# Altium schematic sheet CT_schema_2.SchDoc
size 493 x 398 mm
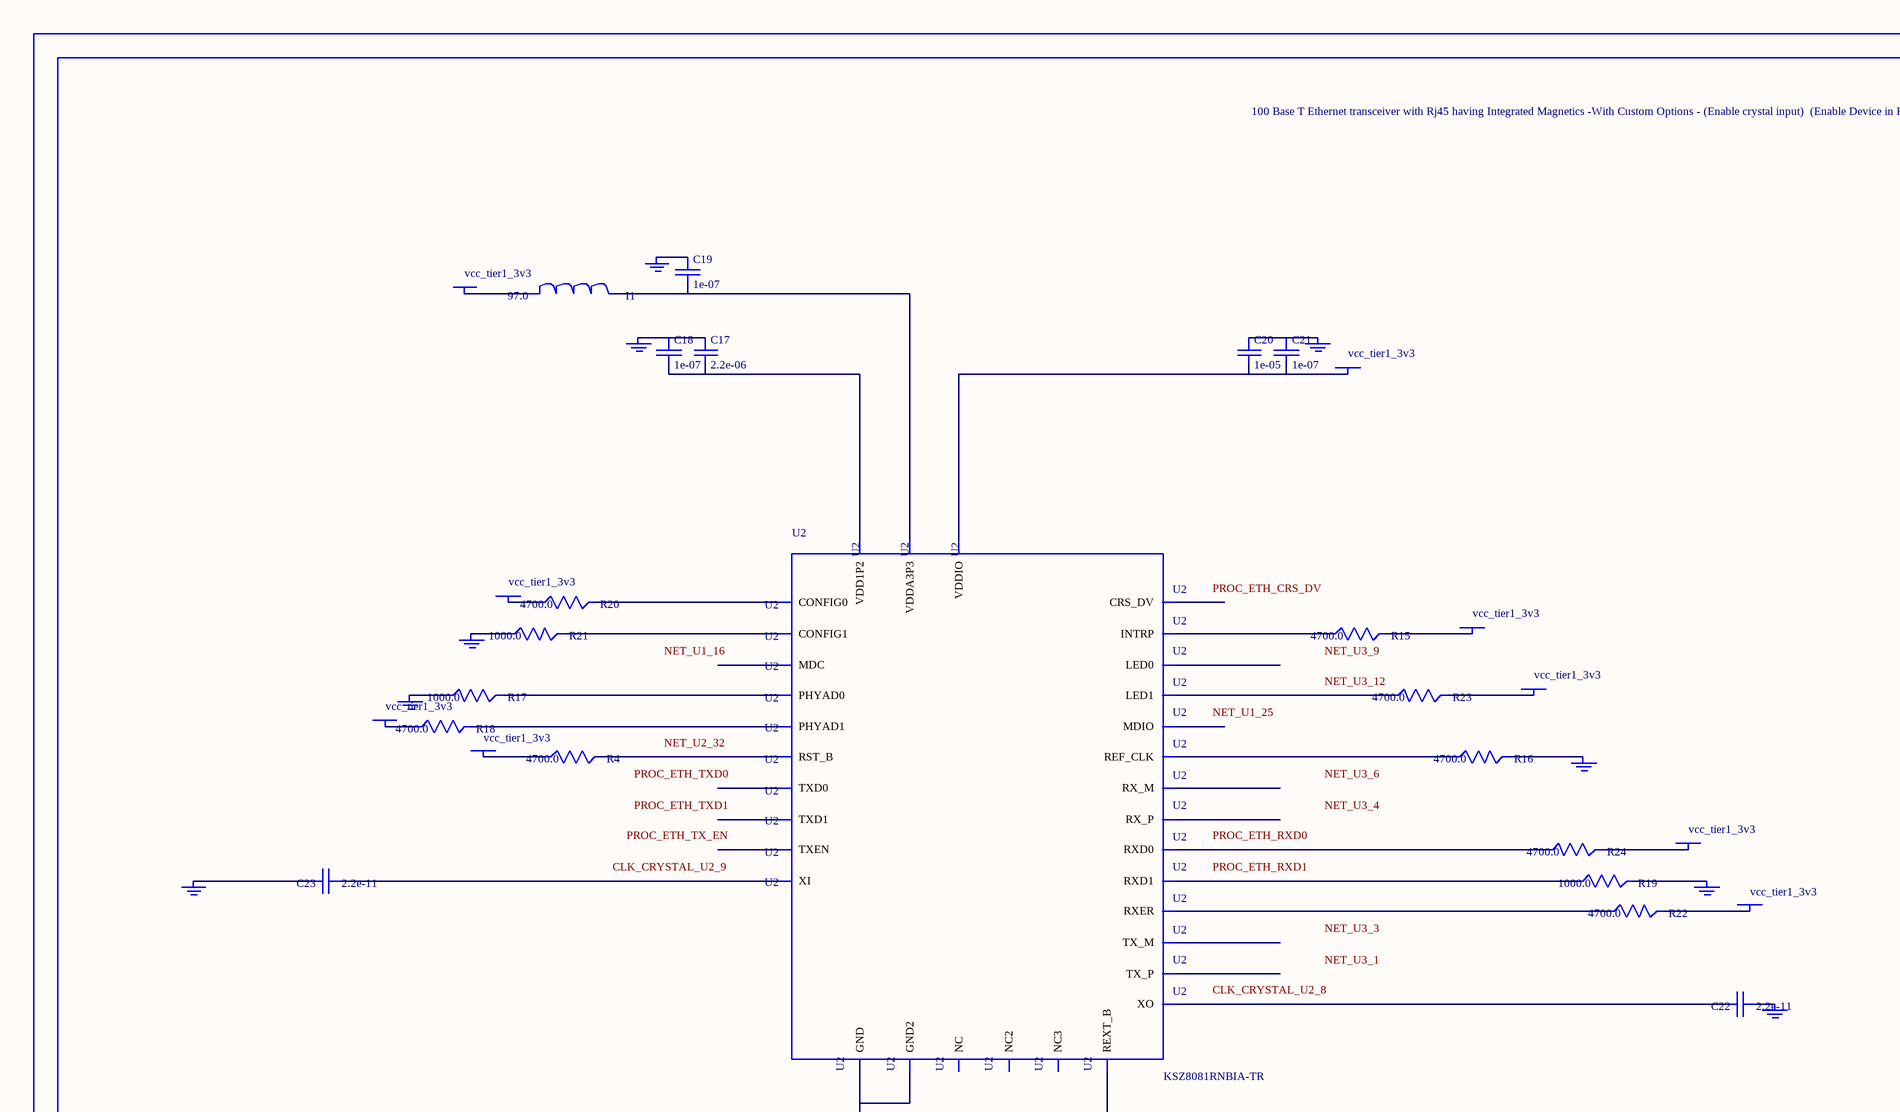
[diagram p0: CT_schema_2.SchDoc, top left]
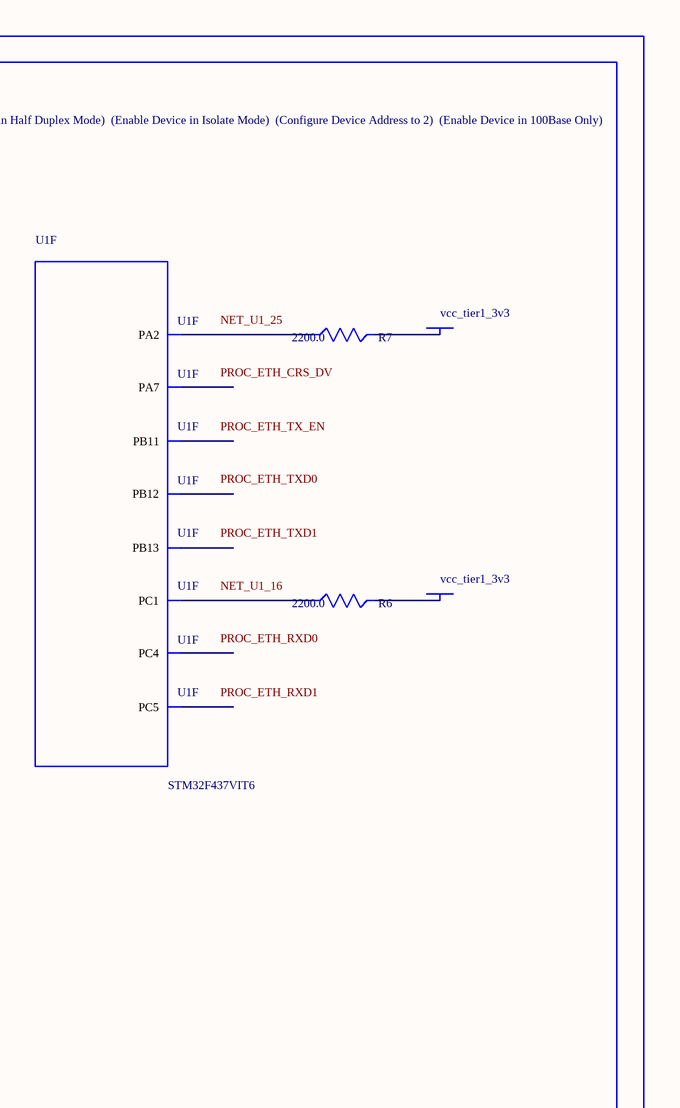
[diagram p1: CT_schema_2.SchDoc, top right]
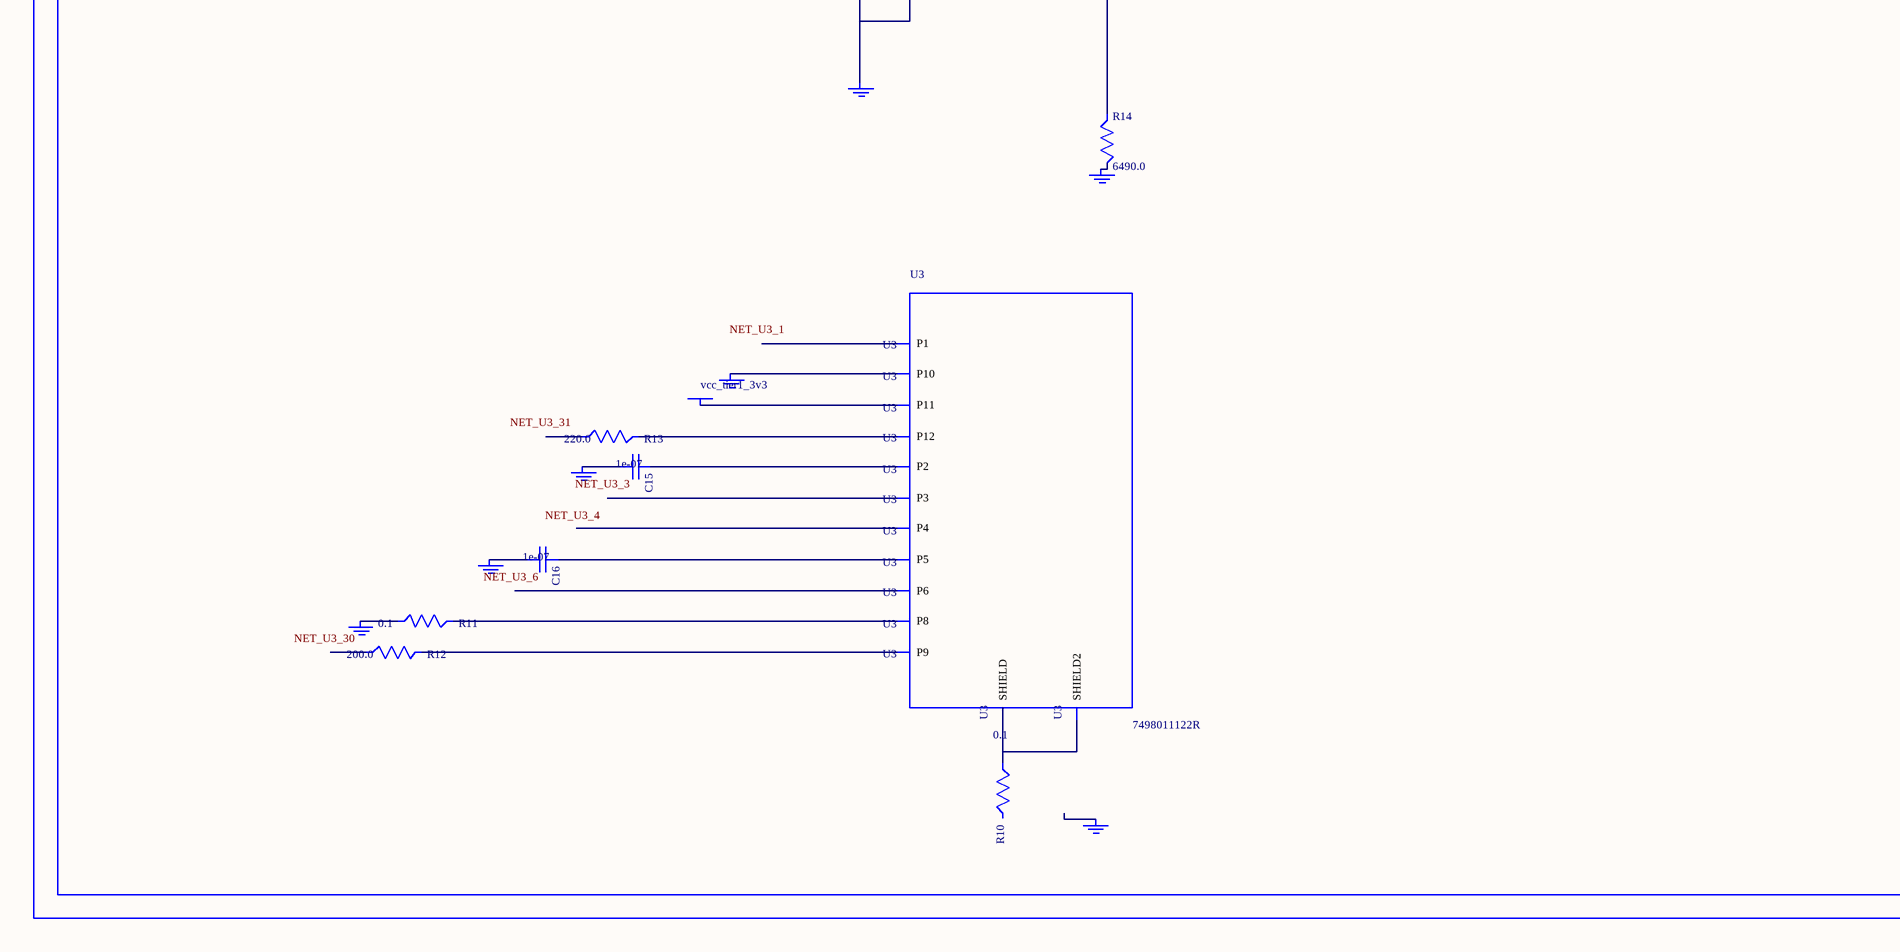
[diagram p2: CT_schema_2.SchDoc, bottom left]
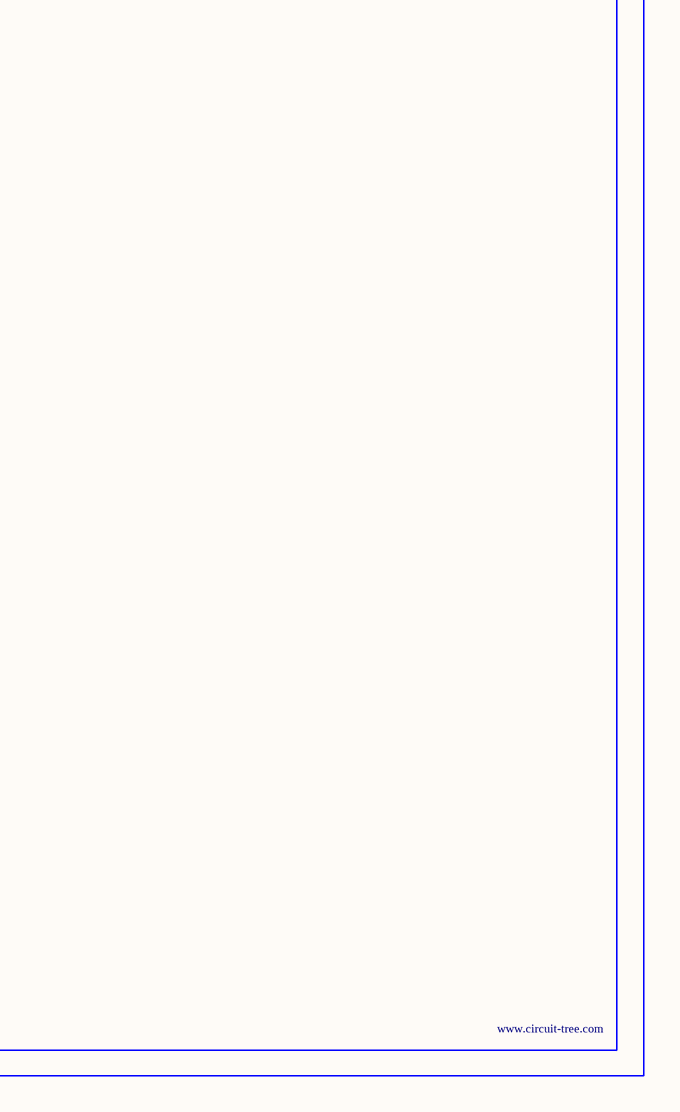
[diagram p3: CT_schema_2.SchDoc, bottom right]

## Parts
BORDER1  (no value)
C15  1e-07  [C0402]
C16  1e-07  [C0402]
C17  2.2e-06  [C0603]
C18  1e-07  [C0402]
C19  1e-07  [C0402]
C20  1e-05  [C0805]
C21  1e-07  [C0402]
C22  2.2e-11  [C0402]
C23  2.2e-11  [C0402]
GND_INSTANCE_1_0  (no value)
GND_INSTANCE_1_1  (no value)
GND_INSTANCE_1_2  (no value)
GND_INSTANCE_1_3  (no value)
GND_INSTANCE_1_4  (no value)
GND_INSTANCE_1_5  (no value)
GND_INSTANCE_1_6  (no value)
GND_INSTANCE_1_7  (no value)
GND_INSTANCE_1_8  (no value)
GND_INSTANCE_1_9  (no value)
GND_INSTANCE_1_10  (no value)
GND_INSTANCE_1_11  (no value)
GND_INSTANCE_1_12  (no value)
GND_INSTANCE_1_13  (no value)
GND_INSTANCE_1_14  (no value)
GND_INSTANCE_1_15  (no value)
I1  97.0  [R0603]
POWER_INSTANCE_1_0  vcc_tier1_3v3
POWER_INSTANCE_1_1  vcc_tier1_3v3
POWER_INSTANCE_1_2  vcc_tier1_3v3
POWER_INSTANCE_1_3  vcc_tier1_3v3
POWER_INSTANCE_1_4  vcc_tier1_3v3
POWER_INSTANCE_1_5  vcc_tier1_3v3
POWER_INSTANCE_1_6  vcc_tier1_3v3
POWER_INSTANCE_1_7  vcc_tier1_3v3
POWER_INSTANCE_1_8  vcc_tier1_3v3
POWER_INSTANCE_1_9  vcc_tier1_3v3
POWER_INSTANCE_1_10  vcc_tier1_3v3
POWER_INSTANCE_1_11  vcc_tier1_3v3
R4  4700.0  [R0603]
R6  2200.0  [R0603]
R7  2200.0  [R0603]
R10  0.1  [R0603]
R11  0.1  [R0603]
R12  200.0  [R0603]
R13  220.0  [R0603]
R14  6490.0  [R0603]
R15  4700.0  [R0603]
R16  4700.0  [R0603]
R17  1000.0  [R0603]
R18  4700.0  [R0603]
R19  1000.0  [R0603]
R20  4700.0  [R0603]
R21  1000.0  [R0603]
R22  4700.0  [R0603]
R23  4700.0  [R0603]
R24  4700.0  [R0603]
U1  STM32F437VIT6  [LQFP100]  (part F of 9)
U2  KSZ8081RNBIA-TR  [QFN-32]
U3  7498011122R  [7498011122R]

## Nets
NetC15_1: C15.1 U3.2(P2)
NetC15_2: C15.2 GND_INSTANCE_1_11.0(GND)
NetC16_1: C16.1 U3.5(P5)
NetC16_2: C16.2 GND_INSTANCE_1_12.0(GND)
NetC17_1: C17.1 C18.1 GND_INSTANCE_1_0.0(GND)
NetC17_2: C17.2 C18.2 U2.2(VDD1P2)
NetC19_1: C19.1 GND_INSTANCE_1_1.0(GND)
NetC19_2: C19.2 I1.2 U2.3(VDDA3P3)
NetC20_1: C20.1 C21.1 GND_INSTANCE_1_7.0(GND)
NetC20_2: C20.2 C21.2 POWER_INSTANCE_1_3.0(PWR) U2.17(VDDIO)
NetC22_1: C22.1 GND_INSTANCE_1_2.0(GND)
NetC22_2: C22.2 U2.8(XO)
NetC23_1: C23.1 U2.9(XI)
NetC23_2: C23.2 GND_INSTANCE_1_3.0(GND)
NetGND_INSTANCE_1_4_0: GND_INSTANCE_1_4.0(GND) R14.2
NetGND_INSTANCE_1_5_0: GND_INSTANCE_1_5.0(GND) R17.1
NetGND_INSTANCE_1_6_0: GND_INSTANCE_1_6.0(GND) R19.2
NetGND_INSTANCE_1_8_0: GND_INSTANCE_1_8.0(GND) R16.2
NetGND_INSTANCE_1_9_0: GND_INSTANCE_1_9.0(GND) R21.1
NetGND_INSTANCE_1_10_0: GND_INSTANCE_1_10.0(GND) U2.1(GND) U2.EXP(GND2)
NetGND_INSTANCE_1_13_0: GND_INSTANCE_1_13.0(GND) R11.1
NetGND_INSTANCE_1_14_0: GND_INSTANCE_1_14.0(GND) U3.10(P10)
NetI1_1: I1.1 POWER_INSTANCE_1_0.0(PWR)
NetPOWER_INSTANCE_1_1_0: POWER_INSTANCE_1_1.0(PWR) R18.1
NetPOWER_INSTANCE_1_2_0: POWER_INSTANCE_1_2.0(PWR) R24.2
NetPOWER_INSTANCE_1_4_0: POWER_INSTANCE_1_4.0(PWR) R22.2
NetPOWER_INSTANCE_1_5_0: POWER_INSTANCE_1_5.0(PWR) R15.2
NetPOWER_INSTANCE_1_6_0: POWER_INSTANCE_1_6.0(PWR) R20.1
NetPOWER_INSTANCE_1_7_0: POWER_INSTANCE_1_7.0(PWR) R23.2
NetPOWER_INSTANCE_1_8_0: POWER_INSTANCE_1_8.0(PWR) R4.1
NetPOWER_INSTANCE_1_9_0: POWER_INSTANCE_1_9.0(PWR) R6.2
NetPOWER_INSTANCE_1_10_0: POWER_INSTANCE_1_10.0(PWR) R7.2
NetPOWER_INSTANCE_1_11_0: POWER_INSTANCE_1_11.0(PWR) U3.11(P11)
NetR4_2: R4.2 U2.32(RST_B)
NetR6_1: R6.1 U1.16(PC1)
NetR7_1: R7.1 U1.25(PA2)
NetR10_1: R10.1 U3.13(SHIELD) U3.14(SHIELD2)
NetR11_2: R11.2 U3.8(P8)
NetR12_2: R12.2 U3.9(P9)
NetR13_2: R13.2 U3.12(P12)
NetR14_1: R14.1 U2.10(REXT_B)
NetR15_1: R15.1 U2.21(INTRP)
NetR16_1: R16.1 U2.19(REF_CLK)
NetR17_2: R17.2 U2.13(PHYAD0)
NetR18_2: R18.2 U2.14(PHYAD1)
NetR19_1: R19.1 U2.15(RXD1)
NetR20_2: R20.2 U2.28(CONFIG0)
NetR21_2: R21.2 U2.29(CONFIG1)
NetR22_1: R22.1 U2.20(RXER)
NetR23_1: R23.1 U2.31(LED1)
NetR24_1: R24.1 U2.16(RXD0)

Not connected (* = marked no-connect by the designer): GND_INSTANCE_1_15 0(GND); R10 2; R12 1; R13 1; U1 32(PA7) 33(PC4) 34(PC5) 48(PB11) 51(PB12) 52(PB13); U2 4(RX_M) 5(RX_P) 6(TX_M) 7(TX_P) 11(MDIO) 12(MDC) 18(CRS_DV) 22(NC) 23(TXEN) 24(TXD0) 25(TXD1) 26(NC2) 27(NC3) 30(LED0); U3 1(P1) 3(P3) 4(P4) 6(P6)

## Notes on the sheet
- Labels drawn without touching a wire or pin: CLK_CRYSTAL_U2_8, CLK_CRYSTAL_U2_9, NET_U1_16, NET_U1_25, NET_U2_32, NET_U3_1, NET_U3_3, NET_U3_4, NET_U3_6, NET_U3_9, NET_U3_12, NET_U3_30, NET_U3_31, PROC_ETH_CRS_DV, PROC_ETH_RXD0, PROC_ETH_RXD1, PROC_ETH_TX_EN, PROC_ETH_TXD0, PROC_ETH_TXD1

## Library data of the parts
BORDER1 = BORDER_PAGE1
C15 C16 C18 C19 C21 = C0402C104K3RACTU
C17 = C0603C225K8RACTU
C20 = C0805C106K8RACTU
C22 C23 = C0402C220K3RAC
GND_INSTANCE_1_0-GND_INSTANCE_1_15 = GND
I1 = I1
POWER_INSTANCE_1_0-POWER_INSTANCE_1_11 = PWR
R4 R15 R16 R18 R20 R22-R24 = RC0603JR-074K7L
R6 R7 = RC0603JR-072K2L
R10 R11 = ERJ-3RSFR10V
R12 = RC0603JR-07200RL
R13 = RC0603JR-07220RL
R14 = ERJ-3EKF6491V
R17 R19 R21 = RC0603JR-071KL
